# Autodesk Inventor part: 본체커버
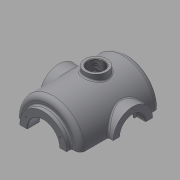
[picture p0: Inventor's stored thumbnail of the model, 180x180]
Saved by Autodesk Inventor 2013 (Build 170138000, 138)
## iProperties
Created: 2016-02
Part Number: 본체커버
Material: 일반
Document SubType Name: Modeling
Designer: mduedu
Density: 1 g/cm^3
Mass: 438.041 g
Surface Area: 904.883 cm^2
Volume: 438.041 cm^3
Author: mduedu
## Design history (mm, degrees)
sketch "스케치2"
  geometry: L1 (0, 90)-(0, -90); L2 (65, -65.993)-(65, 90); L3 (65, 90)-(0, 90); A1 r 100 centre (0, 10) between (0, -90) and (65, -65.993); 2 further points
  constraints: 6 end point, 2 point on circle, 1 centre point, 1 coincident, 1 horizontal, 1 midpoint, 1 parallel, 1 point on line, 1 vertical
  dimensions: "d3" = 180 distance of L1.start L1.end; "d5" = 130 diameter of L2 L1; "d6" = 100 radius of A1
revolve "회전1" sketch "스케치2" stored, may be unused: angle "d7" = 90 deg
sketch "스케치3"
  geometry: C1 r 47.5 at (0, 0); 1 further point
  constraints: 1 centre point, 1 coincident
  dimensions: "d8" = 95 diameter of C1
extrude "돌출2" join sketch "스케치3" distance "d10" = 10; taper "d11" = 0 deg
sketch "스케치5"
  geometry: L1 (47.5, 100)-(47.5, 90) reference; L2 (47.5, 90)-(65, 90) reference; L3 (65, 90)-(65, -65.993) reference; L4 (-65, -65.993)-(-65, 90) reference; L5 (-65, 90)-(-47.5, 90) reference; L6 (-47.5, 90)-(-47.5, 100) reference; L7 (-47.5, 100)-(47.5, 100) reference; L8 (55, 75)-(55, -61.239); L9 (0, 75)-(55, 75); L10 (0, 75)-(0, -80); A1 r 100 centre (0, 10) between (-65, -65.993) and (0, -90) reference; A2 r 100 centre (0, 10) between (0, -90) and (65, -65.993) reference; A3 r 90 centre (0, 10) between (0, -80) and (55, -61.239); 1 further point
  constraints: 6 end point, 2 point on circle, 1 centre point, 1 parallel, 1 perpendicular, 1 point on line, 1 vertical
  dimensions: "d13" = 10 distance between parallel lines of L3 L8; "d14" = 10 radial gap between concentric circles of A3 A1; "d15" = 15 distance between parallel lines of L9 L2
revolve "회전2" sketch "스케치5" stored, may be unused: angle "d16" = 90 deg
hole "구멍1" diameter "d19" = 65; stored, may be unused: countersink angle "d23" = 90 deg, drill point angle "d25" = 118 deg; dims "d17" = 10, "d18" = 10, "d20" = 6, "d21" = 4, "d22" = 2, "d24" = 8
node "작업 평면1"
sketch "스케치6"
  geometry: L1 (47.5, 100)-(-47.5, 100) reference; C1 r 40 at (0, -7); 1 further point
  constraints: 1 centre point, 1 vertical alignment
  dimensions: "d27" = 80 diameter of C1; "d29" = 107 distance from line of C1.centre L1
extrude "돌출3" join sketch "스케치6" stored distance "d30" = 10; taper "d31" = 0 deg
hole "구멍2" diameter "d34" = 42; stored, may be unused: countersink angle "d38" = 90 deg, drill point angle "d40" = 118 deg; dims "d32" = 10, "d33" = 10, "d35" = 6, "d36" = 52, "d37" = 18, "d39" = 8
sketch "스케치7" dims "d41" = 65
  geometry: C1 r 40 at (0, 0) reference; 3 further points
  constraints: 2 vertical alignment, 1 coincident, 2 other
hole "구멍3" sketch "스케치7" at (0, 32.5) diameter "d43" = 3.242; stored, may be unused: countersink angle "d47" = 90 deg, drill point angle "d49" = 118 deg; dims "d44" = 11, "d45" = 13, "d46" = 18, "d48" = 13
sketch "스케치8" dims "d53" = 80
  geometry: 3 further points
  constraints: 2 vertical alignment, 1 coincident, 2 other
hole "구멍4" sketch "스케치8" at (0, -40) diameter "d56" = 3.242; stored, may be unused: countersink angle "d60" = 90 deg, drill point angle "d62" = 118 deg; dims "d57" = 11, "d58" = 13, "d59" = 18, "d61" = 13
fillet "모깎기1" dims "d66" = 10
fillet "모깎기2" dims "d67" = 3
fillet "모깎기3" dims "d68" = 0.3
chamfer "모따기1" distance "d69" = 1; stored, may be unused: second distance "d70" = 2, angle "d71" = 45 deg
node "작업 평면5"
sketch "스케치10"
  geometry: L1 (-50, 66)-(50, 66); L2 (50, 66)-(50, 50); L3 (50, 50)-(-50, 50); L4 (-50, 50)-(-50, 66); 2 further points
  constraints: 8 end point, 2 horizontal, 2 vertical, 1 midpoint, 1 vertical alignment
  dimensions: "d177" = 50 distance from line of L3 point (0, 0); "d178" = 100 distance of L1.start L1.end; "d179" = 16 distance of L3.end L1.start
extrude "돌출5" join sketch "스케치10" stored distance "d84" = 10; taper "d85" = 0 deg
sketch "스케치21" dims "d180" = 220, "d182" = 130
  geometry: L1 (65, 58)-(-65, 58); L2 (-65, 58)-(-65, -32); L3 (-65, -32)-(65, -32); L4 (65, -32)-(65, 58); L5 (50, 50)-(50, 66) reference; 4 further points
  constraints: 8 end point, 3 horizontal alignment, 3 midpoint, 2 parallel, 1 horizontal, 1 perpendicular, 1 vertical alignment, 4 other
extrude "돌출13" join sketch "스케치21" distance "d183" = 10; taper "d184" = 0 deg
sketch "스케치11"
  geometry: L1 (-65, 80)-(-65, -61.239) reference; L2 (-100, -97)-(-100, -32) reference; L3 (-65, -42.793)-(-100, -63); L4 (-100, -97)-(-110, -97) reference; 1 further point
  constraints: 2 end point, 2 point on line
  dimensions: "d185" = 34 distance from line of L3.end L4; "d186" = 120 deg angle of L2 L3
feature "리브1" sketch "스케치11" dims "d88" = 1, "d89" = 16, "d90" = 0, "d91" = 0, "d92" = 1, "d93" = 1
fillet "모깎기12"
fillet "모깎기13"
fillet "모깎기16" dims "d167" = 3
fillet "모깎기18"
fillet "모깎기17" dims "d168" = 3
fillet "모깎기19" dims "d187" = 3
node "작업 평면6"
sketch "스케치19"
  geometry: L1 (75, -47)-(75, 33) reference; L2 (-75, -47)-(-75, 33) reference; L3 (75, -7)-(-75, -7); C1 r 22.5 at (0, -7); 1 further point
  constraints: 3 midpoint, 2 end point, 1 centre point
  dimensions: "d149" = 45 diameter of C1
extrude "돌출11" join sketch "스케치19" stored distance "d150" = 10; taper "d151" = 0 deg
hole "구멍6" diameter "d154" = 33.376; stored, may be unused: countersink angle "d158" = 90 deg, drill point angle "d160" = 118 deg; dims "d155" = 6, "d156" = 4, "d157" = 2, "d159" = 8, "d190" = 10, "d191" = 10
fillet "모깎기11" dims "d161" = 3
chamfer "모따기3" distance "d164" = 1; stored, may be unused: second distance "d165" = 2, angle "d166" = 45 deg
sketch "스케치22" dims "d189" = 20
  geometry: L1 (-10, -123)-(10, -123); L2 (10, -123)-(10, -103); L3 (10, -103)-(-10, -103); L4 (-10, -103)-(-10, -123); A1 r 65 centre (0, -58) between (-65, -58) and (65, -58) reference; 2 further points
  constraints: 8 end point, 2 parallel, 1 horizontal, 1 horizontal alignment, 1 midpoint, 1 perpendicular, 1 tangent, 1 vertical alignment, 2 other
  dimensions: "d193" = 30 dimension on L1
extrude "돌출14" cut sketch "스케치22" stored distance "d194" = 10; taper "d195" = 0 deg
fillet "모깎기21" dims "d196" = 3
feature "분할1"
node "솔리드2"
pattern_circular "원형 패턴1" dims angle "d51" = 360 deg
mirror "대칭1"
pattern_circular "원형 패턴2" dims angle "d64" = 360 deg
node "절단 모서리 투영1"
other parameters: "d26" = 75, "d136" = 175
